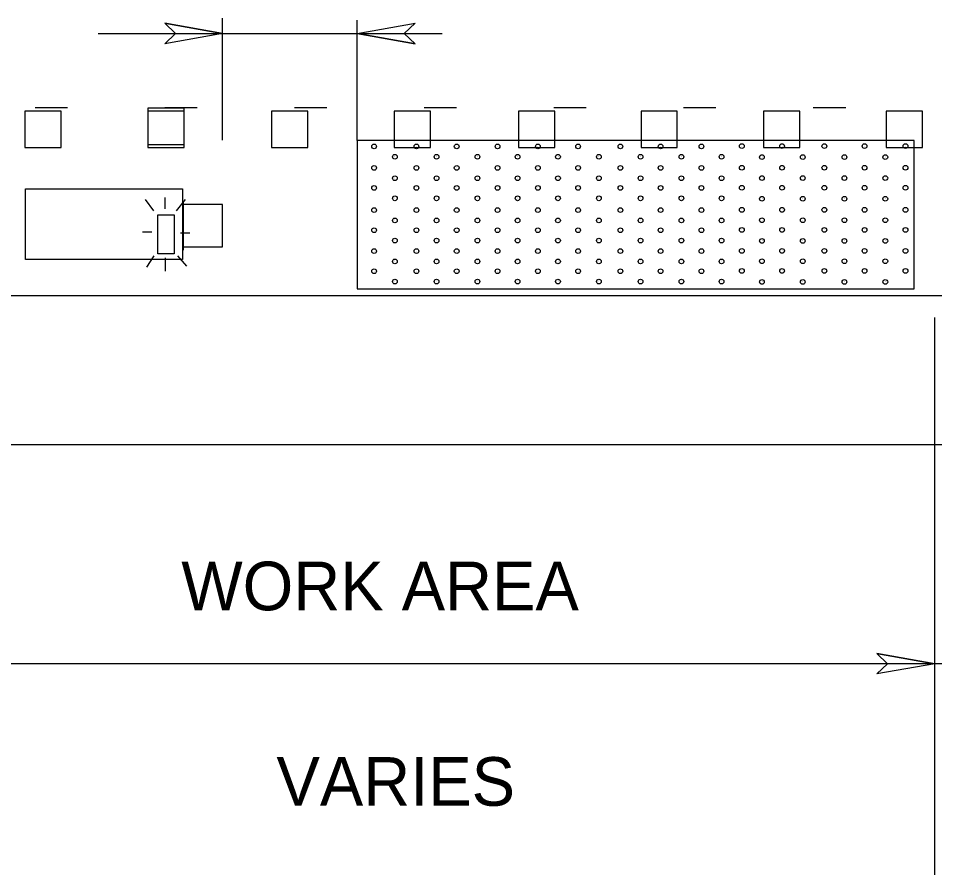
# Model space of a CAD drawing. Extents: x 12.4 to 19.6, y 4 to 16.
# Drawn here: x 17.002 to 18.132, y 10.241 to 11.289 of the extents above; entities that cross this region are included whole.
import ezdxf

# ---------------------------------------------------------------- set-up
doc = ezdxf.new("R2010")
doc.units = 0
for name, color, linetype in [('DETL-DIMS', 7, 'Continuous'), ('DETL-LINE', 7, 'Continuous'), ('DETL-NOTE', 7, 'Continuous'), ('MRKG-LINE', 7, 'Continuous'), ('TTLB-TEXT', 7, 'Continuous'), ('V7_LEVEL_1', 7, 'Continuous')]:
    doc.layers.add(name, color=color, linetype=linetype)

# ---------------------------------------------------------------- blocks, each defined once
blk = doc.blocks.new('BAR')
for p, q in [((-0.11, 0.696), (-0.512, 1.025)), ((0.695, 1.172), (0.695, 0.842)), ((1.5, 0.732), (1.866, 1.062)), ((0.037, 0.037), (0.037, 0.622)), ((0.037, 0.622), (1.427, 0.622)), ((1.427, 0.622), (1.427, 0.037)), ((-0.183, 0.293), (-0.585, 0.293)), ((1.427, 0.037), (0.037, 0.037)), ((1.573, 0.293), (2.049, 0.293)), ((-0.11, -0.11), (-0.512, -0.403)), ((0.658, -0.183), (0.658, -0.513)), ((1.5, -0.11), (1.902, -0.366))]:
    blk.add_line(p, q)

msp = doc.modelspace()

# ---------------------------------------------------------------- linework, layer by layer
at = {"layer": 'DETL-DIMS'}
for p, q in [((17.2538, 11.2698), (17.1823, 11.2824)), ((17.1823, 11.2824), (17.1958, 11.2698)), ((17.2538, 11.1382), (17.2538, 11.2885)), ((17.4197, 11.1378), (17.4197, 11.2861)), ((17.4197, 11.2698), (17.4912, 11.2824)), ((17.4777, 11.2698), (17.4912, 11.2824)), ((17.1003, 11.2698), (17.2538, 11.2698)), ((17.2538, 11.2698), (17.1823, 11.2572)), ((17.1958, 11.2698), (17.1823, 11.2572)), ((17.2451, 11.2698), (17.4892, 11.2698)), ((17.3744, 11.2698), (17.5245, 11.2698)), ((17.4197, 11.2698), (17.4912, 11.2572)), ((17.4912, 11.2572), (17.4777, 11.2698)), ((18.1322, 8.348), (18.1322, 10.9192)), ((18.1322, 10.4922), (18.0607, 10.5048)), ((18.0607, 10.5048), (18.0742, 10.4922)), ((19.0458, 10.4922), (13.3764, 10.4922)), ((18.1322, 10.4922), (18.0607, 10.4796)), ((18.0742, 10.4922), (18.0607, 10.4796))]:
    msp.add_line(p, q, dxfattribs=at)
for points in [[(17.1823, 11.2824), (17.2538, 11.2698), (17.1823, 11.2572), (17.1958, 11.2698)], [(17.4912, 11.2572), (17.4197, 11.2698), (17.4912, 11.2824), (17.4777, 11.2698)], [(18.0607, 10.5048), (18.1322, 10.4922), (18.0607, 10.4796), (18.0742, 10.4922)]]:
    msp.add_lwpolyline(points, close=True, dxfattribs=at)
at = {"layer": 'DETL-LINE'}
for p, q in [((17.4408, 11.1305), (17.4408, 11.1305)), ((17.493, 11.1305), (17.493, 11.1305)), ((17.493, 11.1305), (17.493, 11.1305)), ((17.5426, 11.1305), (17.5426, 11.1305)), ((17.593, 11.1305), (17.593, 11.1305)), ((17.593, 11.1305), (17.593, 11.1305)), ((17.6428, 11.1305), (17.6428, 11.1305)), ((17.6428, 11.1305), (17.6428, 11.1305)), ((17.6924, 11.1305), (17.6924, 11.1305)), ((17.7446, 11.1305), (17.7446, 11.1305)), ((17.7446, 11.1305), (17.7446, 11.1305)), ((17.7942, 11.1305), (17.7942, 11.1305)), ((17.8446, 11.1305), (17.8446, 11.1305)), ((17.8446, 11.1305), (17.8446, 11.1305)), ((17.8944, 11.1308), (17.8944, 11.1308)), ((17.8944, 11.1308), (17.8944, 11.1308)), ((17.944, 11.1308), (17.944, 11.1308)), ((17.9962, 11.1308), (17.9962, 11.1308)), ((17.9962, 11.1308), (17.9962, 11.1308)), ((18.0458, 11.1308), (18.0458, 11.1308)), ((18.0962, 11.1308), (18.0962, 11.1308)), ((18.0962, 11.1308), (18.0962, 11.1308)), ((17.4664, 11.1185), (17.4664, 11.1185)), ((17.4664, 11.1177), (17.4664, 11.1177)), ((17.5178, 11.1185), (17.5178, 11.1185)), ((17.5178, 11.1177), (17.5178, 11.1177)), ((17.5682, 11.1185), (17.5682, 11.1185)), ((17.5682, 11.1177), (17.5682, 11.1177)), ((17.6178, 11.1185), (17.6178, 11.1185)), ((17.6178, 11.1177), (17.6178, 11.1177)), ((17.6676, 11.1185), (17.6676, 11.1185)), ((17.6676, 11.1177), (17.6676, 11.1177)), ((17.718, 11.1185), (17.718, 11.1185)), ((17.718, 11.1177), (17.718, 11.1177)), ((17.7694, 11.1185), (17.7694, 11.1185)), ((17.7694, 11.1177), (17.7694, 11.1177)), ((17.8198, 11.1185), (17.8198, 11.1185)), ((17.8198, 11.1177), (17.8198, 11.1177)), ((17.8694, 11.1185), (17.8694, 11.1185)), ((17.8694, 11.1177), (17.8694, 11.1177)), ((17.9192, 11.118), (17.9192, 11.118)), ((17.9192, 11.1172), (17.9192, 11.1172)), ((17.9696, 11.118), (17.9696, 11.118)), ((17.9696, 11.1172), (17.9696, 11.1172)), ((18.021, 11.118), (18.021, 11.118)), ((18.021, 11.1172), (18.021, 11.1172)), ((18.0714, 11.118), (18.0714, 11.118)), ((18.0714, 11.1172), (18.0714, 11.1172)), ((17.4408, 11.104), (17.4408, 11.104)), ((17.493, 11.104), (17.493, 11.104)), ((17.493, 11.104), (17.493, 11.104)), ((17.5426, 11.104), (17.5426, 11.104)), ((17.593, 11.104), (17.593, 11.104)), ((17.593, 11.104), (17.593, 11.104)), ((17.6428, 11.104), (17.6428, 11.104)), ((17.6428, 11.104), (17.6428, 11.104)), ((17.6924, 11.104), (17.6924, 11.104)), ((17.7446, 11.104), (17.7446, 11.104)), ((17.7446, 11.104), (17.7446, 11.104)), ((17.7942, 11.104), (17.7942, 11.104)), ((17.8446, 11.104), (17.8446, 11.104)), ((17.8446, 11.104), (17.8446, 11.104)), ((17.8944, 11.1043), (17.8944, 11.1043)), ((17.8944, 11.1043), (17.8944, 11.1043)), ((17.944, 11.1043), (17.944, 11.1043)), ((17.9962, 11.1043), (17.9962, 11.1043)), ((17.9962, 11.1043), (17.9962, 11.1043)), ((18.0458, 11.1043), (18.0458, 11.1043)), ((18.0962, 11.1043), (18.0962, 11.1043)), ((18.0962, 11.1043), (18.0962, 11.1043)), ((17.4664, 11.092), (17.4664, 11.092)), ((17.4664, 11.0912), (17.4664, 11.0912)), ((17.5178, 11.092), (17.5178, 11.092)), ((17.5178, 11.0912), (17.5178, 11.0912)), ((17.5682, 11.092), (17.5682, 11.092)), ((17.5682, 11.0912), (17.5682, 11.0912)), ((17.6178, 11.092), (17.6178, 11.092)), ((17.6178, 11.0912), (17.6178, 11.0912)), ((17.6676, 11.092), (17.6676, 11.092)), ((17.6676, 11.0912), (17.6676, 11.0912)), ((17.718, 11.092), (17.718, 11.092)), ((17.718, 11.0912), (17.718, 11.0912)), ((17.7694, 11.092), (17.7694, 11.092)), ((17.7694, 11.0912), (17.7694, 11.0912)), ((17.8198, 11.092), (17.8198, 11.092)), ((17.8198, 11.0912), (17.8198, 11.0912)), ((17.8694, 11.092), (17.8694, 11.092)), ((17.8694, 11.0912), (17.8694, 11.0912)), ((17.9192, 11.0915), (17.9192, 11.0915)), ((17.9192, 11.0915), (17.9192, 11.0915)), ((17.9696, 11.0915), (17.9696, 11.0915)), ((17.9696, 11.0915), (17.9696, 11.0915)), ((18.021, 11.0915), (18.021, 11.0915)), ((18.021, 11.0915), (18.021, 11.0915)), ((18.0714, 11.0915), (18.0714, 11.0915)), ((18.0714, 11.0915), (18.0714, 11.0915)), ((17.4408, 11.0792), (17.4408, 11.0792)), ((17.493, 11.0792), (17.493, 11.0792)), ((17.493, 11.0792), (17.493, 11.0792)), ((17.5426, 11.0792), (17.5426, 11.0792)), ((17.593, 11.0792), (17.593, 11.0792)), ((17.593, 11.0792), (17.593, 11.0792)), ((17.6428, 11.0792), (17.6428, 11.0792)), ((17.6428, 11.0792), (17.6428, 11.0792)), ((17.6924, 11.0792), (17.6924, 11.0792)), ((17.7446, 11.0792), (17.7446, 11.0792)), ((17.7446, 11.0792), (17.7446, 11.0792)), ((17.7942, 11.0792), (17.7942, 11.0792)), ((17.8446, 11.0792), (17.8446, 11.0792)), ((17.8446, 11.0792), (17.8446, 11.0792)), ((17.8944, 11.0795), (17.8944, 11.0795)), ((17.8944, 11.0795), (17.8944, 11.0795)), ((17.944, 11.0795), (17.944, 11.0795)), ((17.9962, 11.0795), (17.9962, 11.0795)), ((17.9962, 11.0795), (17.9962, 11.0795)), ((18.0458, 11.0795), (18.0458, 11.0795)), ((18.0962, 11.0795), (18.0962, 11.0795)), ((18.0962, 11.0795), (18.0962, 11.0795)), ((17.4664, 11.0672), (17.4664, 11.0672)), ((17.4664, 11.0664), (17.4664, 11.0664)), ((17.5178, 11.0672), (17.5178, 11.0672)), ((17.5178, 11.0664), (17.5178, 11.0664)), ((17.5682, 11.0672), (17.5682, 11.0672)), ((17.5682, 11.0664), (17.5682, 11.0664)), ((17.6178, 11.0672), (17.6178, 11.0672)), ((17.6178, 11.0664), (17.6178, 11.0664)), ((17.6676, 11.0672), (17.6676, 11.0672)), ((17.6676, 11.0664), (17.6676, 11.0664)), ((17.718, 11.0672), (17.718, 11.0672)), ((17.718, 11.0664), (17.718, 11.0664)), ((17.7694, 11.0672), (17.7694, 11.0672)), ((17.7694, 11.0664), (17.7694, 11.0664)), ((17.8198, 11.0672), (17.8198, 11.0672)), ((17.8198, 11.0664), (17.8198, 11.0664)), ((17.8694, 11.0672), (17.8694, 11.0672)), ((17.8694, 11.0664), (17.8694, 11.0664)), ((17.9192, 11.0667), (17.9192, 11.0667)), ((17.9192, 11.0659), (17.9192, 11.0659)), ((17.9696, 11.0667), (17.9696, 11.0667)), ((17.9696, 11.0659), (17.9696, 11.0659)), ((18.021, 11.0667), (18.021, 11.0667)), ((18.021, 11.0659), (18.021, 11.0659)), ((18.0714, 11.0667), (18.0714, 11.0667)), ((18.0714, 11.0659), (18.0714, 11.0659)), ((17.4408, 11.0519), (17.4408, 11.0519)), ((17.493, 11.0519), (17.493, 11.0519)), ((17.493, 11.0519), (17.493, 11.0519)), ((17.5426, 11.0519), (17.5426, 11.0519)), ((17.593, 11.0519), (17.593, 11.0519)), ((17.593, 11.0519), (17.593, 11.0519)), ((17.6428, 11.0519), (17.6428, 11.0519)), ((17.6428, 11.0519), (17.6428, 11.0519)), ((17.6924, 11.0519), (17.6924, 11.0519)), ((17.7446, 11.0519), (17.7446, 11.0519)), ((17.7446, 11.0519), (17.7446, 11.0519)), ((17.7942, 11.0519), (17.7942, 11.0519)), ((17.8446, 11.0519), (17.8446, 11.0519)), ((17.8446, 11.0519), (17.8446, 11.0519)), ((17.8944, 11.0522), (17.8944, 11.0522)), ((17.8944, 11.0522), (17.8944, 11.0522)), ((17.944, 11.0522), (17.944, 11.0522)), ((17.9962, 11.0522), (17.9962, 11.0522)), ((17.9962, 11.0522), (17.9962, 11.0522)), ((18.0458, 11.0522), (18.0458, 11.0522)), ((18.0962, 11.0522), (18.0962, 11.0522)), ((18.0962, 11.0522), (18.0962, 11.0522)), ((17.4664, 11.0399), (17.4664, 11.0399)), ((17.4664, 11.0391), (17.4664, 11.0391)), ((17.5178, 11.0399), (17.5178, 11.0399)), ((17.5178, 11.0391), (17.5178, 11.0391)), ((17.5682, 11.0399), (17.5682, 11.0399)), ((17.5682, 11.0391), (17.5682, 11.0391)), ((17.6178, 11.0399), (17.6178, 11.0399)), ((17.6178, 11.0391), (17.6178, 11.0391)), ((17.6676, 11.0399), (17.6676, 11.0399)), ((17.6676, 11.0391), (17.6676, 11.0391)), ((17.718, 11.0399), (17.718, 11.0399)), ((17.718, 11.0391), (17.718, 11.0391)), ((17.7694, 11.0399), (17.7694, 11.0399)), ((17.7694, 11.0391), (17.7694, 11.0391)), ((17.8198, 11.0399), (17.8198, 11.0399)), ((17.8198, 11.0391), (17.8198, 11.0391)), ((17.8694, 11.0399), (17.8694, 11.0399)), ((17.8694, 11.0391), (17.8694, 11.0391)), ((17.9192, 11.0394), (17.9192, 11.0394)), ((17.9192, 11.0394), (17.9192, 11.0394)), ((17.9696, 11.0394), (17.9696, 11.0394)), ((17.9696, 11.0394), (17.9696, 11.0394)), ((18.021, 11.0394), (18.021, 11.0394)), ((18.021, 11.0394), (18.021, 11.0394)), ((18.0714, 11.0394), (18.0714, 11.0394)), ((18.0714, 11.0394), (18.0714, 11.0394)), ((17.4408, 11.0271), (17.4408, 11.0271)), ((17.493, 11.0271), (17.493, 11.0271)), ((17.493, 11.0271), (17.493, 11.0271)), ((17.5426, 11.0271), (17.5426, 11.0271)), ((17.593, 11.0271), (17.593, 11.0271)), ((17.593, 11.0271), (17.593, 11.0271)), ((17.6428, 11.0271), (17.6428, 11.0271)), ((17.6428, 11.0271), (17.6428, 11.0271)), ((17.6924, 11.0271), (17.6924, 11.0271)), ((17.7446, 11.0271), (17.7446, 11.0271)), ((17.7446, 11.0271), (17.7446, 11.0271)), ((17.7942, 11.0271), (17.7942, 11.0271)), ((17.8446, 11.0271), (17.8446, 11.0271)), ((17.8446, 11.0271), (17.8446, 11.0271)), ((17.8944, 11.0274), (17.8944, 11.0274)), ((17.8944, 11.0274), (17.8944, 11.0274)), ((17.944, 11.0274), (17.944, 11.0274)), ((17.9962, 11.0274), (17.9962, 11.0274)), ((17.9962, 11.0274), (17.9962, 11.0274)), ((18.0458, 11.0274), (18.0458, 11.0274)), ((18.0962, 11.0274), (18.0962, 11.0274)), ((18.0962, 11.0274), (18.0962, 11.0274)), ((17.4664, 11.0151), (17.4664, 11.0151)), ((17.4664, 11.0143), (17.4664, 11.0143)), ((17.5178, 11.0151), (17.5178, 11.0151)), ((17.5178, 11.0143), (17.5178, 11.0143)), ((17.5682, 11.0151), (17.5682, 11.0151)), ((17.5682, 11.0143), (17.5682, 11.0143)), ((17.6178, 11.0151), (17.6178, 11.0151)), ((17.6178, 11.0143), (17.6178, 11.0143)), ((17.6676, 11.0151), (17.6676, 11.0151)), ((17.6676, 11.0143), (17.6676, 11.0143)), ((17.718, 11.0151), (17.718, 11.0151)), ((17.718, 11.0143), (17.718, 11.0143)), ((17.7694, 11.0151), (17.7694, 11.0151)), ((17.7694, 11.0143), (17.7694, 11.0143)), ((17.8198, 11.0151), (17.8198, 11.0151)), ((17.8198, 11.0143), (17.8198, 11.0143)), ((17.8694, 11.0151), (17.8694, 11.0151)), ((17.8694, 11.0143), (17.8694, 11.0143)), ((17.9192, 11.0146), (17.9192, 11.0146)), ((17.9192, 11.0138), (17.9192, 11.0138)), ((17.9696, 11.0146), (17.9696, 11.0146)), ((17.9696, 11.0138), (17.9696, 11.0138)), ((18.021, 11.0146), (18.021, 11.0146)), ((18.021, 11.0138), (18.021, 11.0138)), ((18.0714, 11.0146), (18.0714, 11.0146)), ((18.0714, 11.0138), (18.0714, 11.0138)), ((17.4408, 11.0013), (17.4408, 11.0013)), ((17.493, 11.0013), (17.493, 11.0013)), ((17.493, 11.0013), (17.493, 11.0013)), ((17.5426, 11.0013), (17.5426, 11.0013)), ((17.593, 11.0013), (17.593, 11.0013)), ((17.593, 11.0013), (17.593, 11.0013)), ((17.6428, 11.0013), (17.6428, 11.0013)), ((17.6428, 11.0013), (17.6428, 11.0013)), ((17.6924, 11.0013), (17.6924, 11.0013)), ((17.7446, 11.0013), (17.7446, 11.0013)), ((17.7446, 11.0013), (17.7446, 11.0013)), ((17.7942, 11.0013), (17.7942, 11.0013)), ((17.8446, 11.0013), (17.8446, 11.0013)), ((17.8446, 11.0013), (17.8446, 11.0013)), ((17.8944, 11.0016), (17.8944, 11.0016)), ((17.8944, 11.0016), (17.8944, 11.0016)), ((17.944, 11.0016), (17.944, 11.0016)), ((17.9962, 11.0016), (17.9962, 11.0016)), ((17.9962, 11.0016), (17.9962, 11.0016)), ((18.0458, 11.0016), (18.0458, 11.0016)), ((18.0962, 11.0016), (18.0962, 11.0016)), ((18.0962, 11.0016), (18.0962, 11.0016)), ((17.4664, 10.9893), (17.4664, 10.9893)), ((17.4664, 10.9885), (17.4664, 10.9885)), ((17.5178, 10.9893), (17.5178, 10.9893)), ((17.5178, 10.9885), (17.5178, 10.9885)), ((17.5682, 10.9893), (17.5682, 10.9893)), ((17.5682, 10.9885), (17.5682, 10.9885)), ((17.6178, 10.9893), (17.6178, 10.9893)), ((17.6178, 10.9885), (17.6178, 10.9885)), ((17.6676, 10.9893), (17.6676, 10.9893)), ((17.6676, 10.9885), (17.6676, 10.9885)), ((17.718, 10.9893), (17.718, 10.9893)), ((17.718, 10.9885), (17.718, 10.9885)), ((17.7694, 10.9893), (17.7694, 10.9893)), ((17.7694, 10.9885), (17.7694, 10.9885)), ((17.8198, 10.9893), (17.8198, 10.9893)), ((17.8198, 10.9885), (17.8198, 10.9885)), ((17.8694, 10.9893), (17.8694, 10.9893)), ((17.8694, 10.9885), (17.8694, 10.9885)), ((17.9192, 10.9888), (17.9192, 10.9888)), ((17.9192, 10.9888), (17.9192, 10.9888)), ((17.9696, 10.9888), (17.9696, 10.9888)), ((17.9696, 10.9888), (17.9696, 10.9888)), ((18.021, 10.9888), (18.021, 10.9888)), ((18.021, 10.9888), (18.021, 10.9888)), ((18.0714, 10.9888), (18.0714, 10.9888)), ((18.0714, 10.9888), (18.0714, 10.9888)), ((17.4408, 10.9765), (17.4408, 10.9765)), ((17.493, 10.9765), (17.493, 10.9765)), ((17.493, 10.9765), (17.493, 10.9765)), ((17.5426, 10.9765), (17.5426, 10.9765)), ((17.593, 10.9765), (17.593, 10.9765)), ((17.593, 10.9765), (17.593, 10.9765)), ((17.6428, 10.9765), (17.6428, 10.9765)), ((17.6428, 10.9765), (17.6428, 10.9765)), ((17.6924, 10.9765), (17.6924, 10.9765)), ((17.7446, 10.9765), (17.7446, 10.9765)), ((17.7446, 10.9765), (17.7446, 10.9765)), ((17.7942, 10.9765), (17.7942, 10.9765)), ((17.8446, 10.9765), (17.8446, 10.9765)), ((17.8446, 10.9765), (17.8446, 10.9765)), ((17.8944, 10.9768), (17.8944, 10.9768)), ((17.8944, 10.9768), (17.8944, 10.9768)), ((17.944, 10.9768), (17.944, 10.9768)), ((17.9962, 10.9768), (17.9962, 10.9768)), ((17.9962, 10.9768), (17.9962, 10.9768)), ((18.0458, 10.9768), (18.0458, 10.9768)), ((18.0962, 10.9768), (18.0962, 10.9768)), ((18.0962, 10.9768), (18.0962, 10.9768)), ((17.4664, 10.9645), (17.4664, 10.9645)), ((17.4664, 10.9637), (17.4664, 10.9637)), ((17.5178, 10.9645), (17.5178, 10.9645)), ((17.5178, 10.9637), (17.5178, 10.9637)), ((17.5682, 10.9645), (17.5682, 10.9645)), ((17.5682, 10.9637), (17.5682, 10.9637)), ((17.6178, 10.9645), (17.6178, 10.9645)), ((17.6178, 10.9637), (17.6178, 10.9637)), ((17.6676, 10.9645), (17.6676, 10.9645)), ((17.6676, 10.9637), (17.6676, 10.9637)), ((17.718, 10.9645), (17.718, 10.9645)), ((17.718, 10.9637), (17.718, 10.9637)), ((17.7694, 10.9645), (17.7694, 10.9645)), ((17.7694, 10.9637), (17.7694, 10.9637)), ((17.8198, 10.9645), (17.8198, 10.9645)), ((17.8198, 10.9637), (17.8198, 10.9637)), ((17.8694, 10.9645), (17.8694, 10.9645)), ((17.8694, 10.9637), (17.8694, 10.9637)), ((17.9192, 10.964), (17.9192, 10.964)), ((17.9192, 10.9632), (17.9192, 10.9632)), ((17.9696, 10.964), (17.9696, 10.964)), ((17.9696, 10.9632), (17.9696, 10.9632)), ((18.021, 10.964), (18.021, 10.964)), ((18.021, 10.9632), (18.021, 10.9632)), ((18.0714, 10.964), (18.0714, 10.964)), ((18.0714, 10.9632), (18.0714, 10.9632))]:
    msp.add_line(p, q, dxfattribs=at)
for centre in [(17.4407, 11.1305), (17.4929, 11.1305), (17.5425, 11.1305), (17.5929, 11.1305), (17.6427, 11.1305), (17.6923, 11.1305), (17.7445, 11.1305), (17.7941, 11.1305), (17.8445, 11.1305), (17.8943, 11.1308), (17.9439, 11.1308), (17.9961, 11.1308), (18.0457, 11.1308), (18.0962, 11.1308), (17.4663, 11.1177), (17.5177, 11.1177), (17.5681, 11.1177), (17.6177, 11.1177), (17.6675, 11.1177), (17.7179, 11.1177), (17.7693, 11.1177), (17.8197, 11.1177), (17.8693, 11.1177), (17.9191, 11.1172), (17.9695, 11.1172), (18.0209, 11.1172), (18.0713, 11.1172), (17.4407, 11.104), (17.4929, 11.104), (17.5425, 11.104), (17.5929, 11.104), (17.6427, 11.104), (17.6923, 11.104), (17.7445, 11.104), (17.7941, 11.104), (17.8445, 11.104), (17.8943, 11.1042), (17.9439, 11.1042), (17.9961, 11.1042), (18.0457, 11.1042), (18.0962, 11.1042), (17.4663, 11.0912), (17.5177, 11.0912), (17.5681, 11.0912), (17.6177, 11.0912), (17.6675, 11.0912), (17.7179, 11.0912), (17.7693, 11.0912), (17.8197, 11.0912), (17.8693, 11.0912), (17.9191, 11.0914), (17.9695, 11.0914), (18.0209, 11.0914), (18.0713, 11.0914), (17.4407, 11.0792), (17.4929, 11.0792), (17.5425, 11.0792), (17.5929, 11.0792), (17.6427, 11.0792), (17.6923, 11.0792), (17.7445, 11.0792), (17.7941, 11.0792), (17.8445, 11.0792), (17.8943, 11.0794), (17.9439, 11.0794), (17.9961, 11.0794), (18.0457, 11.0794), (18.0962, 11.0794), (17.4663, 11.0664), (17.5177, 11.0664), (17.5681, 11.0664), (17.6177, 11.0664), (17.6675, 11.0664), (17.7179, 11.0664), (17.7693, 11.0664), (17.8197, 11.0664), (17.8693, 11.0664), (17.9191, 11.0658), (17.9695, 11.0658), (18.0209, 11.0658), (18.0713, 11.0658), (17.4407, 11.0519), (17.4929, 11.0519), (17.5425, 11.0519), (17.5929, 11.0519), (17.6427, 11.0519), (17.6923, 11.0519), (17.7445, 11.0519), (17.7941, 11.0519), (17.8445, 11.0519), (17.8943, 11.0522), (17.9439, 11.0522), (17.9961, 11.0522), (18.0457, 11.0522), (18.0962, 11.0522), (17.4663, 11.0391), (17.5177, 11.0391), (17.5681, 11.0391), (17.6177, 11.0391), (17.6675, 11.0391), (17.7179, 11.0391), (17.7693, 11.0391), (17.8197, 11.0391), (17.8693, 11.0391), (17.9191, 11.0394), (17.9695, 11.0394), (18.0209, 11.0394), (18.0713, 11.0394), (17.4407, 11.0271), (17.4929, 11.0271), (17.5425, 11.0271), (17.5929, 11.0271), (17.6427, 11.0271), (17.6923, 11.0271), (17.7445, 11.0271), (17.7941, 11.0271), (17.8445, 11.0271), (17.8943, 11.0274), (17.9439, 11.0274), (17.9961, 11.0274), (18.0457, 11.0274), (18.0962, 11.0274), (17.4663, 11.0143), (17.5177, 11.0143), (17.5681, 11.0143), (17.6177, 11.0143), (17.6675, 11.0143), (17.7179, 11.0143), (17.7693, 11.0143), (17.8197, 11.0143), (17.8693, 11.0143), (17.9191, 11.0138), (17.9695, 11.0138), (18.0209, 11.0138), (18.0713, 11.0138), (17.4407, 11.0013), (17.4929, 11.0013), (17.5425, 11.0013), (17.5929, 11.0013), (17.6427, 11.0013), (17.6923, 11.0013), (17.7445, 11.0013), (17.7941, 11.0013), (17.8445, 11.0013), (17.8943, 11.0016), (17.9439, 11.0016), (17.9961, 11.0016), (18.0457, 11.0016), (18.0962, 11.0016), (17.4663, 10.9885), (17.5177, 10.9885), (17.5681, 10.9885), (17.6177, 10.9885), (17.6675, 10.9885), (17.7179, 10.9885), (17.7693, 10.9885), (17.8197, 10.9885), (17.8693, 10.9885), (17.9191, 10.9888), (17.9695, 10.9888), (18.0209, 10.9888), (18.0713, 10.9888), (17.4407, 10.9765), (17.4929, 10.9765), (17.5425, 10.9765), (17.5929, 10.9765), (17.6427, 10.9765), (17.6923, 10.9765), (17.7445, 10.9765), (17.7941, 10.9765), (17.8445, 10.9765), (17.8943, 10.9768), (17.9439, 10.9768), (17.9961, 10.9768), (18.0457, 10.9768), (18.0962, 10.9768), (17.4663, 10.9637), (17.5177, 10.9637), (17.5681, 10.9637), (17.6177, 10.9637), (17.6675, 10.9637), (17.7179, 10.9637), (17.7693, 10.9637), (17.8197, 10.9637), (17.8693, 10.9637), (17.9191, 10.9632), (17.9695, 10.9632), (18.0209, 10.9632), (18.0713, 10.9632)]:
    msp.add_circle(centre, 0.00291, dxfattribs=at)
at = {"layer": 'MRKG-LINE'}
for p, q in [((17.0624, 11.1781), (17.0224, 11.1781)), ((17.2224, 11.1781), (17.1824, 11.1781)), ((17.2224, 11.1781), (17.1824, 11.1781)), ((17.3824, 11.1781), (17.3424, 11.1781)), ((17.5424, 11.1781), (17.5024, 11.1781)), ((17.7024, 11.1781), (17.6624, 11.1781)), ((17.8624, 11.1781), (17.8224, 11.1781)), ((18.0224, 11.1781), (17.9824, 11.1781)), ((19.5024, 10.9461), (12.7024, 10.9461)), ((19.5024, 10.7623), (12.7024, 10.7623))]:
    msp.add_line(p, q, dxfattribs=at)
for points in [[(17.0099, 11.1741), (17.0099, 11.1293), (17.0547, 11.1293), (17.0547, 11.1741)], [(17.1614, 11.1775), (17.1614, 11.1327), (17.2062, 11.1327), (17.2062, 11.1775)], [(17.1614, 11.1741), (17.1614, 11.1293), (17.2062, 11.1293), (17.2062, 11.1741)], [(17.3141, 11.1741), (17.3141, 11.1293), (17.3589, 11.1293), (17.3589, 11.1741)], [(17.4655, 11.1741), (17.4655, 11.1293), (17.5103, 11.1293), (17.5103, 11.1741)], [(17.6188, 11.1741), (17.6188, 11.1293), (17.6636, 11.1293), (17.6636, 11.1741)], [(17.7699, 11.1741), (17.7699, 11.1293), (17.8147, 11.1293), (17.8147, 11.1741)], [(17.921, 11.1741), (17.921, 11.1293), (17.9658, 11.1293), (17.9658, 11.1741)], [(18.0722, 11.1741), (18.0722, 11.1293), (18.117, 11.1293), (18.117, 11.1741)]]:
    msp.add_lwpolyline(points, close=True, dxfattribs=at)
at = {"layer": 'TTLB-TEXT'}
msp.add_lwpolyline([(17.4197, 10.9546), (18.107, 10.9546), (18.107, 11.1378), (17.4197, 11.1378)], close=True, dxfattribs=at)
at = {"layer": 'V7_LEVEL_1'}
for p, q in [((17.0105, 11.0783), (17.2044, 11.0783)), ((17.0105, 10.9908), (17.0105, 11.0783)), ((17.2044, 11.0783), (17.2044, 10.9908)), ((17.2052, 11.0627), (17.2052, 11.0024)), ((17.2538, 11.0586), (17.2052, 11.0586)), ((17.2538, 11.0065), (17.2538, 11.0586)), ((17.2044, 11.0521), (17.2044, 11.0113)), ((17.2052, 11.0065), (17.2538, 11.0065)), ((17.2044, 10.9908), (17.0105, 10.9908))]:
    msp.add_line(p, q, dxfattribs=at)

# ---------------------------------------------------------------- block references
at = {"layer": 'V7_LEVEL_1', "xscale": 0.03456000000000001, "yscale": 0.03456000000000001, "rotation": -90.00000000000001}
msp.add_blockref('BAR', (17.1726, 11.0473), dxfattribs=at)

# ---------------------------------------------------------------- texts
at = {"layer": 'DETL-NOTE'}
for s, p in [('WORK AREA', (17.2028, 10.5581)), ('VARIES', (17.3202, 10.3169))]:
    msp.add_text(s, height=0.06, rotation=360, dxfattribs=at).set_placement(p)

doc.saveas('drawing.dxf')
